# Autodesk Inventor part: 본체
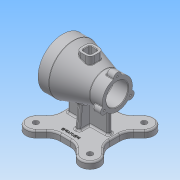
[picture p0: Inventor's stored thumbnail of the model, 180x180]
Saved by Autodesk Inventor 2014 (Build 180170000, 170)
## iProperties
Created: 2018-03
Part Number: 본체
Material: Generic
Document SubType Name: Modeling
Designer: 703
Density: 1 g/cm^3
Appearance: Default
Author: 703
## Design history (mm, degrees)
sketch "스케치1"
  geometry: L1 (-50, 0)-(50, 0); L2 (-50, 0)-(-50, 45); L3 (-50, 45)-(-30, 45); L4 (-30, 45)-(27, 27.5); L5 (27, 27.5)-(50, 27.5); L6 (50, 27.5)-(50, 0); 2 further points
  constraints: 12 end point, 2 parallel, 2 perpendicular, 1 coincident, 1 horizontal, 1 midpoint
  dimensions: "d0" = 100 distance of L1.start L1.end; "d1" = 90 diameter of L3 L1; "d2" = 77 horizontal distance of L4.end L2.end; "d3" = 55 diameter of L5 L1; "d4" = 20 distance of L2.end L3.end
revolve "회전1" sketch "스케치1" stored, may be unused: angle "d5" = 90 deg
node "작업 평면1"
sketch "스케치2"
  geometry: L1 (9.189, -45)-(-9.189, -45); L2 (-45, -9.189)-(-45, 9.189); L3 (-9.189, 45)-(9.189, 45); L4 (45, 9.189)-(45, -9.189); L5 (45, -45)-(-45, 45); L6 (-45, -45)-(45, 45); L7 (0, 0)-(-49.497, 49.497); L8 (-26.866, 52.322)-(-36.77, 62.225); L9 (-62.225, 36.77)-(-52.322, 26.866); L10 (0, 0)-(49.497, 49.497); L11 (52.322, 26.866)-(62.225, 36.77); L12 (36.77, 62.225)-(26.866, 52.322); L13 (0, 0)-(-49.497, -49.497); L14 (-52.322, -26.866)-(-62.225, -36.77); L15 (-36.77, -62.225)-(-26.866, -52.322); L16 (0, 0)-(49.497, -49.497); L17 (26.866, -52.322)-(36.77, -62.225); L18 (62.225, -36.77)-(52.322, -26.866); C1 r 5 at (-49.497, 49.497); C2 r 5 at (-49.497, -49.497); C3 r 5 at (49.497, -49.497); C4 r 5 at (49.497, 49.497); A1 r 18 centre (0, 0) between (-12.728, -12.728) and (12.728, 12.728); A2 r 18 centre (-49.497, 49.497) between (-36.77, 62.225) and (-62.225, 36.77); A3 r 18 centre (0, 0) between (-12.728, 12.728) and (12.728, -12.728); A4 r 18 centre (49.497, 49.497) between (62.225, 36.77) and (36.77, 62.225); A5 r 18 centre (0, 0) between (12.728, -12.728) and (-12.728, 12.728); A6 r 18 centre (-49.497, -49.497) between (-62.225, -36.77) and (-36.77, -62.225); A7 r 18 centre (0, 0) between (12.728, 12.728) and (-12.728, -12.728); A8 r 18 centre (49.497, -49.497) between (36.77, -62.225) and (62.225, -36.77); A9 r 25 centre (-70, 9.189) between (-45, 9.189) and (-52.322, 26.866); A10 r 25 centre (-70, -9.189) between (-52.322, -26.866) and (-45, -9.189); A11 r 25 centre (-9.189, -70) between (-9.189, -45) and (-26.866, -52.322); A12 r 25 centre (9.189, -70) between (26.866, -52.322) and (9.189, -45); A13 r 25 centre (70, -9.189) between (45, -9.189) and (52.322, -26.866); A14 r 25 centre (70, 9.189) between (52.322, 26.866) and (45, 9.189); A15 r 25 centre (9.189, 70) between (9.189, 45) and (26.866, 52.322); A16 r 25 centre (-9.189, 70) between (-26.866, 52.322) and (-9.189, 45); 5 further points
  constraints: 44 end point, 32 point on circle, 32 tangent, 20 centre point, 19 point on line, 7 equal radius, 7 midpoint, 6 parallel, 5 coincident, 3 perpendicular, 1 horizontal
  dimensions: "d7" = 90 distance of L5.end L6.end; "d8" = 90 distance of L6.start L5.end; "d10" = 36 diameter of A2; "d11" = 36 diameter of A4; "d12" = 36 diameter of A6; "d13" = 36 diameter of A8; "d14" = 25 radius of A9; "d15" = 10 diameter of C1; "d16" = 10 diameter of C2; "d17" = 10 diameter of C3; "d18" = 10 diameter of C4; "d19" = 70 distance of point (0, 0) C1.centre; "d20" = 70 distance of point (0, 0) L13.end; "d21" = 70 distance of point (0, 0) L16.end; "d22" = 70 distance of point (0, 0) L10.end
extrude "돌출1" join sketch "스케치2" distance "d23" = 12; taper "d24" = 0 deg
sketch "스케치3"
  geometry: L1 (37, -4)-(-37, -4); L2 (-37, -4)-(-37, 4); L3 (-37, 4)-(37, 4); L4 (37, 4)-(37, -4); L5 (37, -4)-(-37, 4); L6 (-37, -4)-(37, 4); 1 further point
  constraints: 12 end point, 2 midpoint, 2 parallel, 1 horizontal, 1 perpendicular
  dimensions: "d25" = 74 distance of L2.end L3.end; "d26" = 8 distance of L1.end L2.end
extrude "돌출2" join sketch "스케치3" stored distance "d27" = 12; taper "d28" = 0 deg
sketch "스케치4"
  geometry: L1 (-45, -82)-(-45, -70) reference; L2 (-45, -70)-(-4, -70) reference; L3 (-4, -70)-(-4, -35.565) reference; L4 (4, -35.565)-(4, -70) reference; L5 (4, -70)-(45, -70) reference; L6 (45, -70)-(45, -82) reference; L7 (45, -82)-(-45, -82) reference; L8 (-9.189, -70)-(9.189, -70) reference; L9 (0, -70)-(24, -70); L10 (24, -70)-(19.991, -24.175); L11 (0, -70)-(-24, -70); L12 (-24, -70)-(-19.991, -24.175); L13 (-19.991, -24.175)-(19.991, -24.175); A1 r 35.789 centre (0, 0) between (4, -35.565) and (-4, -35.565) reference; 1 further point
  constraints: 10 end point, 2 point on line, 1 midpoint
  dimensions: "d29" = 24 distance of L9.start L9.end; "d30" = 46 distance of L9.end L10.end; "d31" = 85 deg angle of L10 L9; "d32" = 24 distance of L9.start L11.end; "d33" = 46 distance of L11.end L12.end; "d34" = 85 deg angle of L11 L12
extrude "돌출3" join sketch "스케치4" stored distance "d35" = 8; taper "d36" = 0 deg
sketch "스케치5"
  geometry: L1 (-50, 27.5)-(-27, 27.5) reference; L2 (-27, 27.5)-(30, 45) reference; L3 (30, 45)-(50, 45) reference; L4 (50, 45)-(50, -45) reference; L5 (50, -45)-(37, -45) reference; L6 (37, -45)-(37, -70) reference; L7 (37, -70)-(45, -70) reference; L8 (45, -70)-(45, -82) reference; L9 (45, -82)-(-45, -82) reference; L10 (-45, -82)-(-45, -70) reference; L11 (-45, -70)-(-37, -70) reference; L12 (-37, -70)-(-37, -27.5) reference; L13 (-37, -27.5)-(-50, -27.5) reference; L14 (-50, -27.5)-(-50, 27.5) reference; L15 (50, 0)-(-50, 0); L16 (-50, 27.5)-(-50, -27.5) reference; L17 (50, 0)-(50, 35); L18 (50, 45)-(50, -45) reference; L19 (50, 35)-(30, 35); L20 (27, 32)-(27, 29); L21 (30, 45)-(30, -44.822) reference; L22 (24, 26)-(-17, 26); L23 (-20, 23)-(-20, 23); L24 (-23, 20)-(-50, 20); L25 (-50, 0)-(-50, 20); A1 r 3 centre (30, 32) between (30, 35) and (27, 32); A2 r 3 centre (24, 29) between (24, 26) and (27, 29); A3 r 3 centre (-17, 23) between (-17, 26) and (-20, 23); A4 r 3 centre (-23, 23) between (-23, 20) and (-20, 23); 4 further points
  constraints: 16 end point, 8 point on circle, 8 point on line, 8 tangent, 4 centre point, 4 parallel, 3 equal radius, 2 midpoint, 1 collinear, 1 perpendicular
  dimensions: "d37" = 70 diameter of L19 L15; "d38" = 52 diameter of L22 L15; "d39" = 40 diameter of L24 L15; "d40" = 23 distance of L17.end point (27, 35); "d41" = 47 distance of point (27, 26) point (-20, 26); "d42" = 3 radius of A1
revolve "회전2" sketch "스케치5" stored, may be unused: angle "d43" = 90 deg
node "작업 평면2"
sketch "스케치6"
  geometry: L1 (4.5, -12.5)-(-4.5, -12.5); L2 (-12.5, -4.5)-(-12.5, 4.5); L3 (-4.5, 12.5)-(4.5, 12.5); L4 (12.5, 4.5)-(12.5, -4.5); L5 (12.5, -12.5)-(-12.5, 12.5); L6 (-12.5, -12.5)-(12.5, 12.5); A1 r 8 centre (-4.5, 4.5) between (-4.5, 12.5) and (-12.5, 4.5); A2 r 8 centre (-4.5, -4.5) between (-12.5, -4.5) and (-4.5, -12.5); A3 r 8 centre (4.5, -4.5) between (4.5, -12.5) and (12.5, -4.5); A4 r 8 centre (4.5, 4.5) between (12.5, 4.5) and (4.5, 12.5); 1 further point
  constraints: 12 end point, 8 point on circle, 8 point on line, 8 tangent, 4 centre point, 3 equal radius, 2 midpoint, 2 parallel, 1 horizontal, 1 perpendicular
  dimensions: "d45" = 25 distance of L5.end L6.end; "d46" = 25 distance of L6.start L5.end; "d47" = 8 radius of A1
extrude "돌출4" join sketch "스케치6" stored distance "d48" = 8; taper "d49" = 0 deg
sketch "스케치7"
  geometry: L1 (4.5, -7.5)-(-4.5, -7.5); L2 (-7.5, -4.5)-(-7.5, 4.5); L3 (-4.5, 7.5)-(4.5, 7.5); L4 (7.5, 4.5)-(7.5, -4.5); L5 (7.5, -7.5)-(-7.5, 7.5); L6 (-7.5, -7.5)-(7.5, 7.5); A1 r 3 centre (-4.5, 4.5) between (-4.5, 7.5) and (-7.5, 4.5); A2 r 3 centre (-4.5, -4.5) between (-7.5, -4.5) and (-4.5, -7.5); A3 r 3 centre (4.5, -4.5) between (4.5, -7.5) and (7.5, -4.5); A4 r 3 centre (4.5, 4.5) between (7.5, 4.5) and (4.5, 7.5); 1 further point
  constraints: 12 end point, 8 point on circle, 8 point on line, 8 tangent, 4 centre point, 3 equal radius, 2 midpoint, 2 parallel, 1 horizontal, 1 perpendicular
  dimensions: "d50" = 15 distance of L5.end L6.end; "d51" = 15 distance of L6.start L5.end; "d52" = 3 radius of A1
extrude "돌출5" cut sketch "스케치7" distance "d53" = 30; taper "d54" = 0 deg
fillet "모깎기1" dims "d55" = 1
sketch "스케치8"
  geometry: C1 r 35 at (0, 0) reference; 6 further points
  constraints: 1 horizontal alignment, 7 other
  dimensions: "d56" = 40 distance of C1.centre point (40, 0); "d59" = 360 deg dimension on C1.centre point (40, 0) (derived)
hole "구멍1" sketch "스케치8" at (40, 0), (20, 34.641), (-20, 34.641), (-40, 0), (-20, -34.641), (20, -34.641) diameter "d61" = 3.242; stored, may be unused: countersink angle "d65" = 90 deg, drill point angle "d67" = 118 deg; dims "d62" = 9, "d63" = 4, "d64" = 2, "d66" = 11
sketch "스케치9"
  geometry: L1 (0, 0)-(-27.5, 0); L2 (0, 0)-(13.75, -23.816); L3 (0, 0)-(27.5, 0); L4 (0, 0)-(13.75, 23.816); L5 (0, 0)-(27.5, 0); C1 r 27.5 at (0, 0); A1 r 27.5 centre (0, 0) between (7.292, -26.516) and (19.317, -19.573) reference; A2 r 7 centre (-27.5, 0) between (-26.609, 6.943) and (-26.609, -6.943); A3 r 7 centre (13.75, -23.816) between (7.292, -26.516) and (19.317, -19.573); A4 r 7 centre (13.75, 23.816) between (19.317, 19.573) and (7.292, 26.516)
  constraints: 12 point on circle, 10 end point, 4 centre point, 4 coincident, 3 horizontal, 2 equal length
  dimensions: "d68" = 55 diameter of C1; "d69" = 27.5 distance of L1.start L1.end; "d70" = 27.5 distance of L1.start L2.end; "d71" = 60 deg angle of L2 L3; "d72" = 27.5 distance of L1.start L4.end; "d73" = 60 deg angle of L5 L4; "d74" = 14 diameter of A2; "d75" = 14 diameter of A3; "d76" = 14 diameter of A4
extrude "돌출6" join sketch "스케치9" distance "d77" = 15; taper "d78" = 0 deg
sketch "스케치10"
  geometry: A1 r 7 centre (0, 0) between (0.891, 6.943) and (0.891, -6.943) reference; A2 r 7 centre (41.25, -23.816) between (34.792, -26.516) and (46.817, -19.573) reference; A3 r 7 centre (41.25, 23.816) between (46.817, 19.573) and (34.792, 26.516) reference; 3 further points
  constraints: 3 coincident
hole "구멍2" sketch "스케치10" at (0, 0), (41.25, -23.816), (41.25, 23.816) diameter "d79" = 3.242; stored, may be unused: countersink angle "d83" = 90 deg, drill point angle "d85" = 118 deg; dims "d80" = 9, "d81" = 4, "d82" = 2, "d84" = 11
fillet "모깎기2" dims "d86" = 3
fillet "모깎기3" dims "d87" = 1
fillet "모깎기4" dims "d88" = 3
chamfer "모따기1" distance "d89" = 1; stored, may be unused: second distance "d90" = 2, angle "d91" = 45 deg
chamfer "모따기2" distance "d92" = 1; stored, may be unused: second distance "d93" = 2, angle "d94" = 45 deg
fillet "모깎기5" dims "d95" = 3
fillet "모깎기6" dims "d96" = 3
fillet "모깎기7" dims "d97" = 3
sketch "스케치11"
  geometry: L1 (45, -9.189)-(45, 9.189) reference; 2 further points
  constraints: 1 other
  dimensions: "d98" = 45 distance from line of L1 point (0, -35); "d99" = 35 distance of point (0, -35) point (0, 0)
feature "엠보싱1" sketch "스케치11" dims "d0" = 100, "d1" = 90, "d2" = 77, "d3" = 55, "d4" = 20, "d7" = 90, "d8" = 90, "d10" = 36, "d11" = 36, "d12" = 36, "d13" = 36, "d14" = 25, "d15" = 10, "d16" = 10, "d17" = 10, "d18" = 10, "d19" = 70, "d20" = 70, "d21" = 70, "d22" = 70, "d100" = 0.5, "d101" = 0
node "솔리드1"
node "절단 모서리 투영1"
node "절단 모서리 투영2"
other parameters: "d6" = -82, "d44" = 45
